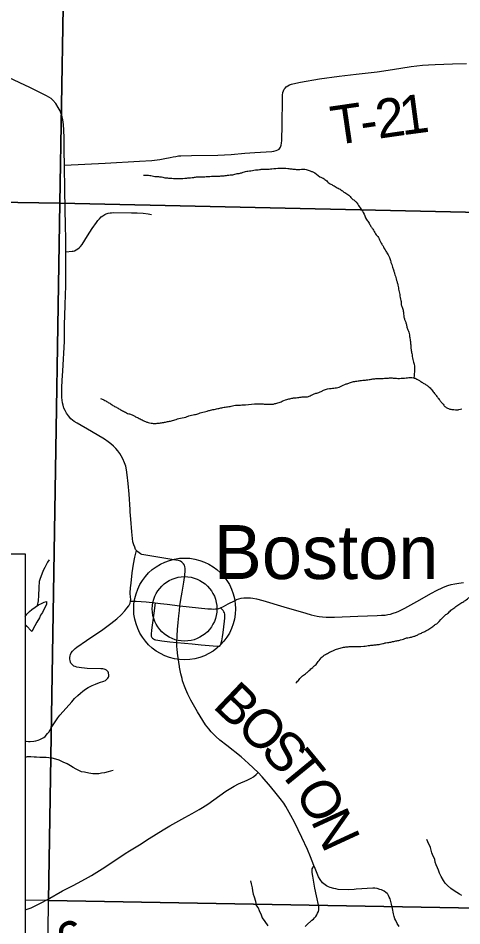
# Model space of a CAD drawing. Extents: x 0 to 34, y 0 to 22.
# Drawn here: x 28.802 to 29.451, y 15.474 to 16.803 of the extents above; entities that cross this region are included whole.
import ezdxf

# ---------------------------------------------------------------- set-up
doc = ezdxf.new("R2010")
doc.units = 0
for name, color, linetype in [('GM_X_Corporation', 7, 'Continuous'), ('GM_X_County_Road', 7, 'Continuous'), ('GM_X_County_Road_Text', 7, 'Continuous'), ('GM_X_Minor_River', 7, 'Continuous'), ('GM_X_Township_Road', 7, 'Continuous'), ('GM_X_Township_Road_Text', 7, 'Continuous'), ('GM_X_Unincorporated', 7, 'Continuous'), ('GM_X_Unincorporated_Location', 7, 'Continuous'), ('GM_X_Unincorporated_Text', 7, 'Continuous'), ('SH_Data', 7, 'Continuous')]:
    doc.layers.add(name, color=color, linetype=linetype)

msp = doc.modelspace()

# ---------------------------------------------------------------- linework, layer by layer
at = {"layer": 'GM_X_Corporation'}
for points in [[(27.873, 17.5549), (28.8799, 17.5369), (28.863, 16.5324), (27.8467, 16.5483)], [(28.8799, 17.5369), (29.9011, 17.5188), (29.8741, 16.51), (28.863, 16.5324)], [(29.8741, 16.51), (29.8543, 15.4933), (28.8464, 15.5116), (28.863, 16.5324)], [(28.8464, 15.5116), (29.8543, 15.4933), (29.8316, 14.4749), (28.8354, 14.4926)]]:
    msp.add_lwpolyline(points, close=True, dxfattribs=at)
msp.add_lwpolyline([(27.8369, 16.0188), (27.8467, 16.5483), (28.863, 16.5324), (28.8464, 15.5116), (28.8122, 15.5121)], dxfattribs=at)
at = {"layer": 'GM_X_County_Road'}
for points in [[(28.9751, 16.0238), (28.9738, 16.0254), (28.9724, 16.0285), (28.9709, 16.0322), (28.9697, 16.0363), (28.969, 16.0413), (28.9681, 16.051), (28.9667, 16.0695), (28.966, 16.0804), (28.9658, 16.0838), (28.9643, 16.1062), (28.9629, 16.1219), (28.9615, 16.1347), (28.9604, 16.1419), (28.9592, 16.1475), (28.9576, 16.1521), (28.9551, 16.158), (28.9527, 16.1624), (28.9505, 16.1659), (28.9478, 16.1695), (28.9446, 16.1733), (28.9414, 16.1767), (28.9374, 16.1802), (28.9335, 16.1831), (28.9281, 16.1866), (28.909, 16.1978), (28.8882, 16.21), (28.8839, 16.2129), (28.879, 16.2168), (28.8755, 16.2209), (28.8727, 16.2247), (28.8705, 16.2286), (28.8689, 16.2321), (28.8676, 16.2367), (28.867, 16.24), (28.866, 16.2478), (28.8656, 16.2557), (28.8658, 16.2626), (28.8665, 16.2725), (28.8675, 16.2869), (28.8695, 16.3298), (28.8699, 16.3544), (28.8707, 16.3823), (28.8712, 16.3991), (28.8715, 16.4099), (28.8719, 16.4528), (28.8717, 16.4612), (28.8715, 16.4808), (28.8713, 16.4984), (28.8703, 16.5508), (28.8697, 16.5877), (28.8693, 16.6089), (28.8691, 16.6279), (28.8688, 16.6391), (28.8682, 16.6474), (28.8673, 16.6543), (28.8664, 16.6584), (28.8651, 16.6629), (28.8634, 16.6672), (28.8607, 16.6725), (28.8569, 16.6782), (28.8529, 16.6828), (28.85, 16.6853), (28.8466, 16.6876), (28.8433, 16.6895), (28.8188, 16.7017), (28.789, 16.7158)], [(29.0341, 15.8891), (29.0346, 15.899), (29.0352, 15.9084), (29.0361, 15.9186), (29.0369, 15.9282), (29.0377, 15.936), (29.0385, 15.9428), (29.04, 15.9521), (29.0417, 15.9629), (29.0441, 15.9777), (29.0456, 15.9876), (29.0462, 15.994), (29.0461, 15.9974), (29.0457, 16.0002), (29.0451, 16.0023), (29.044, 16.0042), (29.043, 16.0054), (29.0415, 16.0068), (29.0392, 16.008), (29.0365, 16.009), (29.0328, 16.0096), (28.9859, 16.0175), (28.983, 16.0182), (28.9808, 16.0192), (28.979, 16.0202), (28.9769, 16.0218), (28.9751, 16.0238)], [(29.038, 15.8543), (29.037, 15.8604), (29.0352, 15.8735), (29.0345, 15.8801), (29.0342, 15.883), (29.0341, 15.8858), (29.0341, 15.8891)], [(29.0451, 15.8253), (29.0436, 15.8293), (29.0424, 15.833), (29.0416, 15.8367), (29.0401, 15.8431), (29.0381, 15.8533), (29.038, 15.8543)], [(29.3593, 15.4735), (29.3563, 15.4777), (29.3541, 15.4821), (29.353, 15.4849), (29.3519, 15.4882), (29.3511, 15.4921), (29.3495, 15.4996), (29.3482, 15.5062), (29.3472, 15.5102), (29.346, 15.5138), (29.3448, 15.5166), (29.3436, 15.519), (29.3424, 15.5207), (29.3415, 15.5218), (29.3398, 15.5233), (29.3371, 15.5252), (29.3335, 15.527), (29.3311, 15.5278), (29.3271, 15.5289), (29.3237, 15.5294), (29.3206, 15.5296), (29.2965, 15.5281), (29.2934, 15.5278), (29.2848, 15.5273), (29.2701, 15.5278), (29.2665, 15.5284), (29.2637, 15.529), (29.2583, 15.5307), (29.256, 15.5316), (29.2531, 15.533), (29.2508, 15.5346), (29.2472, 15.5376), (29.2436, 15.5422), (29.2412, 15.5464), (29.2362, 15.5586), (29.2346, 15.5628), (29.2297, 15.5755), (29.2251, 15.5862), (29.2168, 15.6039), (29.2059, 15.626), (29.2006, 15.6362), (29.1959, 15.6446), (29.1934, 15.6493), (29.1904, 15.6539), (29.1853, 15.661), (29.1794, 15.6683), (29.171, 15.6784), (29.1588, 15.6924), (29.1529, 15.6989), (29.1389, 15.7122), (29.1279, 15.7217), (29.1071, 15.7383), (29.0971, 15.7464), (29.0909, 15.7518), (29.0843, 15.7585), (29.0807, 15.7628), (29.0762, 15.7688), (29.072, 15.7751), (29.0642, 15.7879), (29.0546, 15.8046), (29.0501, 15.8136), (29.047, 15.8203), (29.0451, 15.8253)]]:
    msp.add_lwpolyline(points, dxfattribs=at)
at = {"layer": 'GM_X_Minor_River'}
msp.add_line((28.8135, 15.9143), (28.8122, 15.9123), dxfattribs=at)
for points in [[(28.8474, 16.0104), (28.8448, 16.0066), (28.843, 16.0027), (28.8408, 15.9989), (28.8386, 15.9947), (28.8364, 15.989), (28.8342, 15.9829), (28.8328, 15.9783), (28.8322, 15.9696), (28.8323, 15.9658), (28.8316, 15.9616), (28.8317, 15.9578), (28.831, 15.9502), (28.8297, 15.9432)], [(28.8122, 15.927), (28.8147, 15.9306), (28.8184, 15.9345), (28.8222, 15.9376), (28.827, 15.9411), (28.8315, 15.9445), (28.836, 15.9465), (28.8398, 15.9481), (28.8435, 15.9493), (28.8436, 15.9455), (28.8418, 15.9417), (28.8392, 15.9367), (28.8374, 15.9329), (28.8348, 15.9291), (28.833, 15.9252), (28.8293, 15.9191), (28.8264, 15.9137), (28.8222, 15.9051)], [(28.8222, 15.9051), (28.8135, 15.9143), (28.8122, 15.9157)], [(28.9409, 15.702), (28.9371, 15.7008), (28.9334, 15.6999), (28.9281, 15.6983), (28.9239, 15.6979), (28.9198, 15.6971), (28.9111, 15.6969), (28.9054, 15.6979), (28.8989, 15.6993), (28.8948, 15.7), (28.8906, 15.7018), (28.8868, 15.7037), (28.8826, 15.7062), (28.8787, 15.7088), (28.8738, 15.7118), (28.868, 15.714), (28.8619, 15.7169), (28.857, 15.7183), (28.8517, 15.7197), (28.8467, 15.7204), (28.843, 15.7207), (28.838, 15.721), (28.8339, 15.7209), (28.8289, 15.7212), (28.8252, 15.7215), (28.8206, 15.7218), (28.8149, 15.7217), (28.8122, 15.721)], [(29.4511, 15.5189), (29.4473, 15.5207), (29.4396, 15.5255), (29.4347, 15.5292), (29.43, 15.5333), (29.4266, 15.5371), (29.4242, 15.5408), (29.4204, 15.5468), (29.4184, 15.5517), (29.4168, 15.5558), (29.4152, 15.5596), (29.4132, 15.5637), (29.412, 15.5679), (29.4112, 15.572), (29.4089, 15.5765), (29.4069, 15.5814), (29.4061, 15.5852), (29.4049, 15.589), (29.4009, 15.5972), (29.3997, 15.601)], [(29.142, 15.5403), (29.1428, 15.5358), (29.144, 15.5301), (29.1449, 15.5256), (29.1457, 15.5206), (29.1473, 15.5169), (29.1489, 15.5105), (29.1502, 15.5044), (29.1529, 15.5007), (29.1545, 15.4969), (29.1572, 15.4905), (29.1588, 15.4864), (29.1627, 15.4808), (29.1673, 15.4744)]]:
    msp.add_lwpolyline(points, dxfattribs=at)
for points in [[(28.9852, 16.5732), (28.989, 16.5732), (28.9962, 16.5726), (29, 16.5719), (29.0041, 16.5712), (29.0102, 16.5709), (29.0167, 16.5695), (29.0205, 16.5692), (29.0265, 16.5686), (29.0485, 16.569), (29.0541, 16.5695), (29.0587, 16.5699), (29.0643, 16.5708), (29.0749, 16.571), (29.0821, 16.5715), (29.0927, 16.5717), (29.0984, 16.5721), (29.1048, 16.5726), (29.1119, 16.5735), (29.1172, 16.574), (29.121, 16.5752), (29.1267, 16.5761), (29.1312, 16.5777), (29.138, 16.5793), (29.1425, 16.5798), (29.1466, 16.5806), (29.1512, 16.581), (29.1549, 16.5815), (29.1602, 16.582), (29.1648, 16.582), (29.1731, 16.5826), (29.1965, 16.583), (29.2022, 16.5823), (29.2087, 16.5817), (29.2189, 16.5819), (29.2231, 16.5816), (29.2288, 16.5794), (29.233, 16.578), (29.2433, 16.5709), (29.2494, 16.568), (29.2544, 16.5636), (29.2594, 16.5599), (29.264, 16.5577), (29.2701, 16.554), (29.2754, 16.551), (29.2796, 16.5477), (29.2858, 16.544), (29.2896, 16.5395), (29.2938, 16.5362), (29.2973, 16.5325), (29.302, 16.5254), (29.3066, 16.5186), (29.3113, 16.5085), (29.3152, 16.5029), (29.318, 16.498), (29.3207, 16.4942), (29.3246, 16.4875), (29.3288, 16.4819), (29.3324, 16.4747), (29.3351, 16.4702), (29.3398, 16.462), (29.3429, 16.4567), (29.3452, 16.4526), (29.3469, 16.4466), (29.3484, 16.4424), (29.3496, 16.4386), (29.3512, 16.4334), (29.3525, 16.4292), (29.3537, 16.4255), (29.3561, 16.4172), (29.3573, 16.4122), (29.3589, 16.4043), (29.3598, 16.4005), (29.361, 16.3918), (29.3619, 16.3881), (29.3623, 16.3835), (29.3639, 16.3786), (29.3655, 16.3726), (29.366, 16.3665), (29.3672, 16.362), (29.3688, 16.3582), (29.37, 16.3533), (29.3713, 16.3481), (29.3732, 16.3435), (29.3741, 16.3394), (29.3749, 16.3345), (29.3758, 16.328), (29.3763, 16.322), (29.3767, 16.3178), (29.3776, 16.3122), (29.3784, 16.308), (29.3792, 16.3035), (29.3804, 16.2993), (29.3806, 16.2764)], [(28.9224, 16.2464), (28.9273, 16.2442), (28.9327, 16.2413), (28.9369, 16.2387), (28.9419, 16.2354), (28.9468, 16.2328), (28.9518, 16.2299), (28.9575, 16.2269), (28.9636, 16.224), (28.9686, 16.2226), (28.9724, 16.2204), (28.9777, 16.2178), (28.9835, 16.2149), (28.988, 16.2127), (28.9922, 16.2112), (28.9964, 16.2102), (29.0021, 16.2099), (29.0085, 16.2104), (29.0149, 16.2113), (29.0202, 16.2125), (29.0262, 16.2137), (29.033, 16.2158), (29.0368, 16.217), (29.047, 16.219), (29.0515, 16.221), (29.0598, 16.2227), (29.0662, 16.2243), (29.0699, 16.2259), (29.0744, 16.2267), (29.0782, 16.2279), (29.0831, 16.2292), (29.0869, 16.23), (29.094, 16.2316), (29.0997, 16.2329), (29.1065, 16.2341), (29.1137, 16.235), (29.1216, 16.2367), (29.1272, 16.2368), (29.1344, 16.2373), (29.1518, 16.2387), (29.1586, 16.2385), (29.1651, 16.2378), (29.1689, 16.2379), (29.1741, 16.238), (29.1787, 16.2392), (29.1851, 16.2408), (29.1907, 16.2436), (29.1948, 16.2448), (29.2009, 16.2464), (29.2061, 16.2473), (29.2107, 16.2477), (29.2175, 16.2486), (29.2224, 16.2487), (29.2277, 16.2496), (29.2337, 16.2527), (29.2386, 16.2543), (29.245, 16.2567), (29.2487, 16.2587), (29.26, 16.2611), (29.2676, 16.262), (29.2713, 16.2629), (29.2796, 16.2668), (29.2841, 16.2684), (29.2894, 16.2704), (29.2958, 16.2716), (29.3022, 16.2725), (29.3098, 16.2734), (29.3169, 16.2743), (29.3218, 16.2751), (29.3286, 16.2756), (29.3358, 16.2758), (29.3434, 16.2763), (29.3472, 16.2764), (29.3536, 16.2761), (29.3574, 16.2758), (29.3619, 16.2759), (29.3672, 16.2763), (29.3714, 16.2768), (29.3755, 16.2769), (29.3801, 16.2766), (29.385, 16.2748), (29.3888, 16.2726), (29.3934, 16.2696), (29.3976, 16.267), (29.4015, 16.2644), (29.4069, 16.2588), (29.4111, 16.2536), (29.4142, 16.2495), (29.4177, 16.245), (29.4208, 16.2409), (29.4243, 16.2368), (29.4281, 16.2331), (29.4323, 16.2313), (29.4373, 16.2302), (29.4414, 16.2299), (29.4467, 16.23), (29.4509, 16.2312)], [(29.2081, 15.8299), (29.2129, 15.835), (29.2177, 15.8404), (29.2237, 15.8446), (29.2278, 15.8481), (29.2327, 15.8528), (29.2364, 15.8559), (29.2408, 15.8612), (29.2468, 15.8682), (29.2528, 15.8724), (29.2588, 15.8756), (29.2659, 15.8787), (29.2727, 15.8811), (29.2764, 15.882), (29.2828, 15.8828), (29.2897, 15.8833), (29.3074, 15.8837), (29.3161, 15.885), (29.3199, 15.8854), (29.3256, 15.8859), (29.3312, 15.8867), (29.3354, 15.8876), (29.3399, 15.8888), (29.344, 15.8893), (29.3497, 15.8905), (29.3557, 15.8917), (29.3614, 15.893), (29.3655, 15.8942), (29.37, 15.8958), (29.3742, 15.8966), (29.3798, 15.8979), (29.3843, 15.8995), (29.3888, 15.9018), (29.3945, 15.9042), (29.3994, 15.9069), (29.4057, 15.9108), (29.4109, 15.9147), (29.4151, 15.9174), (29.4255, 15.9282), (29.4299, 15.9317), (29.4348, 15.9364), (29.4404, 15.9406), (29.4467, 15.9449), (29.4524, 15.9484), (29.4572, 15.9516), (29.4647, 15.9566), (29.4685, 15.9578), (29.4722, 15.9594), (29.4775, 15.9603), (29.4817, 15.9607), (29.4862, 15.9604), (29.4908, 15.9594), (29.4957, 15.9579), (29.501, 15.9565), (29.5079, 15.9544), (29.5143, 15.953), (29.5215, 15.952), (29.5253, 15.9517), (29.531, 15.951), (29.5356, 15.9515), (29.5393, 15.9511), (29.5564, 15.9515), (29.5605, 15.9527), (29.5673, 15.9539), (29.5737, 15.9559), (29.5775, 15.9568), (29.5835, 15.9584), (29.5903, 15.9604), (29.5948, 15.9624), (29.5997, 15.9636), (29.6034, 15.9644), (29.6087, 15.9664), (29.6147, 15.9684), (29.6189, 15.97), (29.6237, 15.9716), (29.6279, 15.974), (29.6324, 15.9759), (29.6361, 15.9783), (29.6402, 15.981), (29.644, 15.9834), (29.6485, 15.9865), (29.6529, 15.9915), (29.6551, 15.9953), (29.6569, 15.9995), (29.6598, 16.0068), (29.6609, 16.011), (29.6627, 16.0163), (29.6645, 16.0201), (29.6663, 16.0266), (29.6685, 16.0316), (29.6706, 16.0392), (29.6732, 16.0442), (29.6757, 16.0506), (29.6783, 16.0549), (29.6801, 16.0606), (29.6852, 16.0694), (29.6867, 16.0732)]]:
    msp.add_spline(points, degree=3, dxfattribs=at)
at = {"layer": 'GM_X_Township_Road'}
for points in [[(28.8697, 16.5877), (28.9292, 16.5908), (28.9794, 16.5935), (28.9974, 16.5949), (29.0092, 16.5962), (29.0164, 16.5974), (29.0244, 16.5991), (29.0289, 16.6001), (29.0325, 16.6007), (29.0363, 16.6013), (29.04, 16.6016), (29.0553, 16.6019), (29.0942, 16.6025), (29.1134, 16.6035), (29.1333, 16.6053), (29.1483, 16.6063), (29.1731, 16.6081), (29.1761, 16.6085), (29.1793, 16.6093), (29.1818, 16.6104), (29.1836, 16.6114), (29.1855, 16.614), (29.1866, 16.617), (29.1873, 16.6199), (29.1877, 16.624), (29.1881, 16.6468), (29.1884, 16.6851), (29.1887, 16.6904), (29.1892, 16.694), (29.19, 16.6968), (29.1912, 16.6991), (29.1923, 16.7006), (29.194, 16.7026), (29.1988, 16.7053), (29.2017, 16.7064), (29.2082, 16.7081), (29.2148, 16.7094), (29.2427, 16.714), (29.2714, 16.718), (29.2965, 16.7211), (29.3268, 16.7245), (29.3494, 16.7279), (29.377, 16.7322), (29.3932, 16.7341), (29.4023, 16.7348), (29.4117, 16.7353), (29.437, 16.736), (29.4579, 16.7367)], [(28.8717, 16.4612), (28.8808, 16.4619), (28.8826, 16.4622), (28.8844, 16.4627), (28.8868, 16.4639), (28.8894, 16.4655), (28.891, 16.4668), (28.8933, 16.4687), (28.8956, 16.4719), (28.9033, 16.4844), (28.9103, 16.4953), (28.9164, 16.5039), (28.9185, 16.5067), (28.9209, 16.5094), (28.9236, 16.5121), (28.9259, 16.5139), (28.9289, 16.5156), (28.9309, 16.5165), (28.9337, 16.5174), (28.9363, 16.518), (28.9383, 16.5183), (28.9416, 16.5186), (28.9675, 16.5183), (28.9762, 16.518), (28.9847, 16.5174), (28.992, 16.5165), (28.9972, 16.5156)], [(28.9665, 15.9497), (28.9667, 15.9519), (28.9665, 15.9558), (28.9661, 15.9575), (28.9659, 15.9593), (28.9658, 15.9618), (28.9662, 15.969), (28.967, 15.9762), (28.9688, 15.9911), (28.9706, 16.0038), (28.9725, 16.0142), (28.9751, 16.0238)], [(29.0977, 15.9399), (29.1021, 15.942), (29.1093, 15.9456), (29.1183, 15.9504), (29.1215, 15.9521), (29.1246, 15.9533), (29.1283, 15.9542), (29.1319, 15.9546), (29.1353, 15.9548), (29.142, 15.9546), (29.1452, 15.9542), (29.1505, 15.9532), (29.16, 15.9506), (29.1907, 15.9414), (29.2227, 15.932), (29.2305, 15.9298), (29.2351, 15.9287), (29.2393, 15.9278), (29.2424, 15.9273), (29.2473, 15.9268), (29.2524, 15.9265), (29.2561, 15.9263), (29.2603, 15.9262), (29.2644, 15.9263), (29.299, 15.9277), (29.3272, 15.9288), (29.3333, 15.929), (29.3386, 15.9294), (29.3426, 15.93), (29.3467, 15.9309), (29.3503, 15.932), (29.3551, 15.9336), (29.3587, 15.9351), (29.3675, 15.9395), (29.3852, 15.9491), (29.4067, 15.9614), (29.4137, 15.9652), (29.4231, 15.9699), (29.4265, 15.9713), (29.4303, 15.9726), (29.4353, 15.9739), (29.4406, 15.975), (29.4463, 15.976), (29.4534, 15.9772)], [(28.8122, 15.745), (28.8137, 15.7447), (28.817, 15.7444), (28.8195, 15.7443), (28.8247, 15.7447), (28.8278, 15.7452), (28.8313, 15.7461), (28.8338, 15.7471), (28.8366, 15.7485), (28.8393, 15.7502), (28.8414, 15.7518), (28.845, 15.756), (28.8466, 15.7581), (28.8514, 15.7659), (28.8549, 15.7718), (28.86, 15.7789), (28.8629, 15.7827), (28.8677, 15.7884), (28.8803, 15.8023), (28.8846, 15.807), (28.889, 15.8114), (28.8931, 15.8152), (28.8967, 15.8181), (28.9005, 15.8211), (28.9042, 15.8233), (28.9102, 15.8263), (28.9152, 15.8284), (28.9209, 15.8304), (28.9274, 15.8328), (28.9296, 15.8338), (28.9313, 15.835), (28.9331, 15.8369), (28.934, 15.8383), (28.9344, 15.8397), (28.9346, 15.8413), (28.9342, 15.8449), (28.9337, 15.8462), (28.9323, 15.8475), (28.931, 15.8485), (28.9292, 15.8495), (28.9279, 15.85), (28.9256, 15.8505), (28.9228, 15.8507), (28.9028, 15.8513), (28.8988, 15.8515), (28.8947, 15.8519), (28.8912, 15.8524), (28.888, 15.8531), (28.8852, 15.8539), (28.8836, 15.8547), (28.882, 15.8558), (28.8804, 15.8574), (28.8792, 15.8591), (28.8785, 15.8606), (28.8778, 15.8626), (28.8775, 15.8647), (28.8776, 15.8672), (28.878, 15.8697), (28.8787, 15.8718), (28.8797, 15.874), (28.8814, 15.8763), (28.8831, 15.8782), (28.8853, 15.8803), (28.8879, 15.8822), (28.9019, 15.8919), (28.9257, 15.9084), (28.9376, 15.9169), (28.9464, 15.924), (28.9528, 15.9296), (28.9579, 15.9353), (28.961, 15.9392), (28.9637, 15.9428), (28.9649, 15.9448), (28.9658, 15.9467), (28.9665, 15.9497)], [(28.9665, 15.9497), (28.9748, 15.9496), (28.9891, 15.9485), (29.0023, 15.9474), (29.01, 15.9464)], [(29.0023, 15.9474), (29.0003, 15.9319), (28.9981, 15.9145), (28.9971, 15.9072), (28.9965, 15.9015), (28.9966, 15.8987), (28.997, 15.8975), (28.9976, 15.8965)], [(29.01, 15.9464), (29.0198, 15.9452), (29.0385, 15.9428)], [(29.0385, 15.9428), (29.0796, 15.9387), (29.0847, 15.9383), (29.088, 15.9381), (29.0905, 15.9383), (29.0933, 15.9387), (29.0954, 15.9391), (29.0977, 15.9399)], [(29.0972, 15.8847), (29.0978, 15.8856), (29.0984, 15.8869), (29.0991, 15.8888), (29.0998, 15.8918), (29.1007, 15.8977), (29.1017, 15.904), (29.1039, 15.9206), (29.1043, 15.9248), (29.1042, 15.9308), (29.1039, 15.9324), (29.1029, 15.9343), (29.1018, 15.9359), (29.0977, 15.9399)], [(28.9976, 15.8965), (28.9985, 15.8954), (28.9998, 15.8944), (29.0012, 15.8937), (29.003, 15.8931), (29.0062, 15.8926), (29.0122, 15.8918), (29.0238, 15.8904), (29.0341, 15.8891), (29.0564, 15.8871), (29.0694, 15.8857), (29.0871, 15.8841), (29.0929, 15.8836), (29.0949, 15.8837), (29.096, 15.884), (29.0972, 15.8847)], [(28.8122, 15.498), (28.8153, 15.499), (28.8208, 15.501), (28.8279, 15.5041), (28.8358, 15.5079), (28.8447, 15.5128), (28.8668, 15.5256), (28.8822, 15.5337), (28.8953, 15.5405), (28.9047, 15.5456), (28.9092, 15.5482), (28.9249, 15.5579), (28.9418, 15.5693), (28.9587, 15.5802), (28.965, 15.5842), (28.9792, 15.5932), (28.9934, 15.6022), (29.0139, 15.615), (29.0237, 15.6209), (29.0368, 15.6283), (29.0455, 15.6331), (29.0565, 15.639), (29.0668, 15.6447), (29.0718, 15.6476), (29.0792, 15.6527), (29.088, 15.6587), (29.1058, 15.6714), (29.1108, 15.6746), (29.1181, 15.6789), (29.1244, 15.6823), (29.1368, 15.6878), (29.1398, 15.6891), (29.1429, 15.6907), (29.1461, 15.6927), (29.1503, 15.6962), (29.1529, 15.6989)], [(29.2215, 15.4734), (29.2235, 15.4753), (29.2316, 15.4826), (29.2337, 15.4843), (29.2356, 15.4862), (29.2373, 15.4883), (29.2388, 15.4905), (29.24, 15.4929), (29.241, 15.4953), (29.2417, 15.4979), (29.2418, 15.4999), (29.2415, 15.5027), (29.2383, 15.5183), (29.2361, 15.5297), (29.2328, 15.5473), (29.232, 15.5526), (29.2318, 15.5559), (29.2321, 15.5579), (29.2327, 15.5596), (29.2346, 15.5628)]]:
    msp.add_lwpolyline(points, dxfattribs=at)
at = {"layer": 'GM_X_Unincorporated'}
for radius in [0.0744, 0.0472]:
    msp.add_circle((29.0454, 15.9384), radius, dxfattribs=at)
at = {"layer": 'GM_X_Unincorporated_Location'}
msp.add_line((29.0454, 15.9384), (29.0454, 15.9384), dxfattribs=at)
at = {"layer": 'SH_Data'}
msp.add_lwpolyline([(27.5407, 16.0188), (28.8122, 16.0188), (28.8122, 15.3888), (27.5407, 15.3888)], close=True, dxfattribs=at)

# ---------------------------------------------------------------- texts
at = {"layer": 'GM_X_County_Road_Text'}
for s, rotation, p in [('B', 316.4408, (29.0849, 15.795)), ('O', 316.2507, (29.1187, 15.7629)), ('S', 313.8442, (29.1544, 15.7287)), ('T', 309.3345, (29.1802, 15.702)), ('O', 298.9808, (29.2056, 15.6713)), ('N', 294.794, (29.2293, 15.6286))]:
    msp.add_text(s, height=0.0568, rotation=rotation, dxfattribs=at).set_placement(p)
at = {"layer": 'GM_X_Township_Road_Text'}
for s, rotation, p in [('2', 8.1721, (29.3289, 16.6265)), ('1', 7.6175, (29.3634, 16.6315)), ('T', 8.285, (29.2637, 16.617)), ('-', 8.2675, (29.3058, 16.6232)), ('6', 29.5294, (28.8785, 15.4185))]:
    msp.add_text(s, height=0.0568, rotation=rotation, dxfattribs=at).set_placement(p)
at = {"layer": 'GM_X_Unincorporated_Text'}
msp.add_text('Boston', height=0.07898, rotation=0, dxfattribs=at).set_placement((29.0879, 15.9821))

doc.saveas('drawing.dxf')
